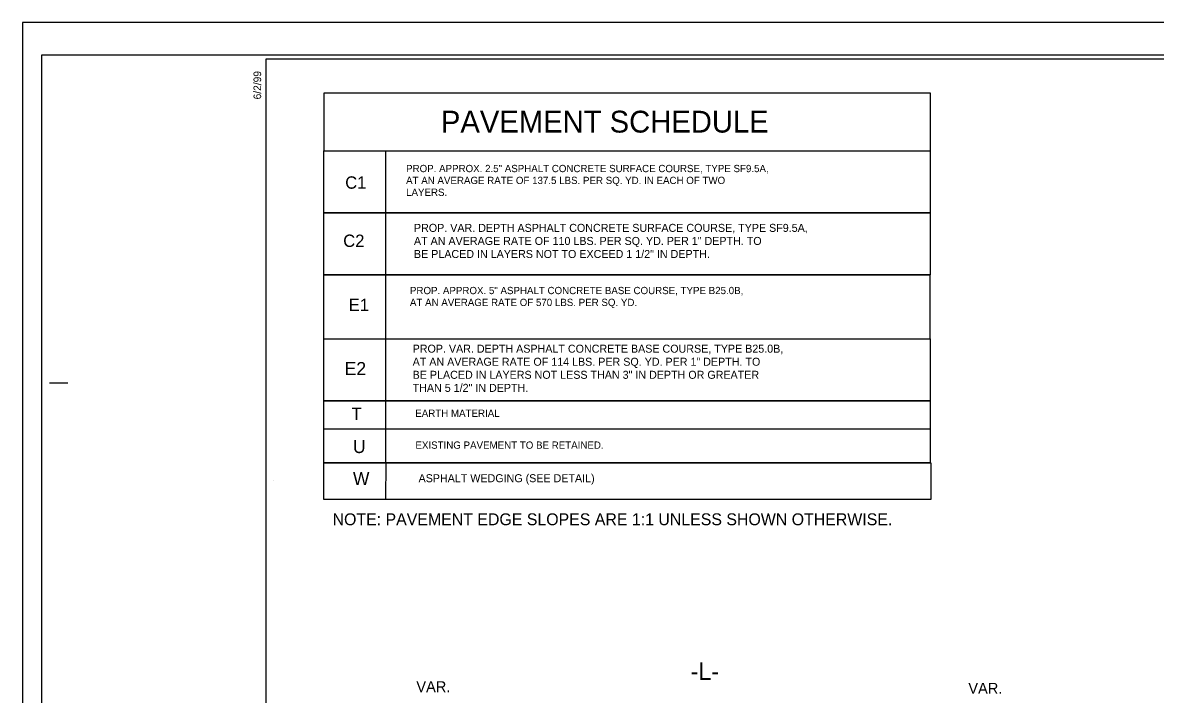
# Model space of a CAD drawing. Extents: x 1818040 to 1825768, y 638918 to 648046.
# Drawn here: x 1820393 to 1821171, y 646022 to 646483 of the extents above; entities that cross this region are included whole.
import ezdxf

# ---------------------------------------------------------------- set-up
doc = ezdxf.new("R2010")
doc.units = 0
for name, color, linetype in [('Prop Pavement Schedule Description CELL', 7, 'Continuous'), ('Sheet Data Field CELL', 7, 'Continuous'), ('Sheet Plot Border Inside CELL', 7, 'Continuous'), ('Sheet Plot Border Outside CELL', 7, 'Continuous'), ('Sheet Typical CELL', 7, 'Continuous')]:
    doc.layers.add(name, color=color, linetype=linetype)

msp = doc.modelspace()

# ---------------------------------------------------------------- linework, layer by layer
at = {"layer": 'Prop Pavement Schedule Description CELL'}
for p, q in [((1820599.79, 646352.71), (1820999.8, 646352.71)), ((1820599.79, 646310.1), (1821016.4, 646310.1)), ((1820599.79, 646266.3), (1820599.79, 646310.1)), ((1820642.4, 646266.3), (1820642.4, 646310.1)), ((1821016.4, 646266.3), (1821016.4, 646310.1)), ((1820599.79, 646204.46), (1821016.4, 646204.46)), ((1820642.4, 646181.09), (1820642.26, 646155.89)), ((1820565.07, 646169.1), (1820565.07, 646169.1))]:
    msp.add_line(p, q, dxfattribs=at)
for points in [[(1820599.79, 646395.32), (1821016.64, 646395.32), (1821016.64, 646435.08), (1820599.79, 646435.08)], [(1820599.79, 646181.09), (1821016.73, 646181.09), (1821016.73, 646155.89), (1820599.79, 646155.89)]]:
    msp.add_lwpolyline(points, close=True, dxfattribs=at)
for points in [[(1820642.4, 646352.71), (1820599.79, 646352.71), (1820599.79, 646395.32), (1821016.39, 646395.32), (1821016.39, 646352.71), (1820642.4, 646352.71), (1820642.4, 646395.32)], [(1820642.4, 646310.1), (1820599.79, 646310.1), (1820599.79, 646352.71), (1821016.39, 646352.71), (1821016.39, 646310.1), (1820642.4, 646310.1), (1820642.4, 646352.71)], [(1820642.4, 646223.69), (1820599.79, 646223.69), (1820599.79, 646266.3), (1821016.4, 646266.3), (1821016.4, 646223.69), (1820642.4, 646223.69), (1820642.4, 646266.3)], [(1820642.4, 646181.09), (1820599.79, 646181.09), (1820599.79, 646223.69), (1821016.4, 646223.69), (1821016.4, 646181.09), (1820642.4, 646181.09), (1820642.4, 646223.69)]]:
    msp.add_lwpolyline(points, dxfattribs=at)
at = {"layer": 'Sheet Plot Border Inside CELL'}
msp.add_lwpolyline([(1822072.43, 646461.05), (1820405.93, 646461.05), (1820405.93, 645405.95), (1822072.43, 645405.95)], close=True, dxfattribs=at)
at = {"layer": 'Sheet Plot Border Outside CELL'}
msp.add_lwpolyline([(1822076.93, 646483.5), (1820392.93, 646483.5), (1820392.93, 645383.5), (1822076.93, 645383.5)], close=True, dxfattribs=at)
at = {"layer": 'Sheet Typical CELL'}
for p, q in [((1822076.93, 646483.5), (1820392.93, 646483.5)), ((1820392.93, 646483.5), (1820392.93, 645383.5)), ((1820411.43, 646236), (1820423.93, 646236))]:
    msp.add_line(p, q, dxfattribs=at)
msp.add_lwpolyline([(1822059.93, 646458.5), (1820559.93, 646458.5), (1820559.93, 645408.5), (1822059.93, 645408.5)], close=True, dxfattribs=at)

# ---------------------------------------------------------------- texts
at = {"layer": 'Prop Pavement Schedule Description CELL'}
for s, height, p in [('PAVEMENT SCHEDULE', 15, (1820680.27, 646407.95)), ('PROP. APPROX. 2.5" ASPHALT CONCRETE SURFACE COURSE, TYPE SF9.5A, ', 5, (1820656.35, 646380.75)), ('C1', 8.506, (1820614.52, 646369.37)), ('AT AN AVERAGE RATE OF 137.5 LBS. PER SQ. YD. IN EACH OF TWO ', 5, (1820656.35, 646372.59)), ('LAYERS.', 5, (1820656.35, 646364.43)), ('PROP. VAR. DEPTH ASPHALT CONCRETE SURFACE COURSE, TYPE SF9.5A,', 5.5, (1820661.74, 646339.71)), ('C2', 8.506, (1820613.16, 646329.34)), ('AT AN AVERAGE RATE OF 110 LBS. PER SQ. YD. PER 1" DEPTH. TO', 5.5, (1820661.74, 646330.73)), ('BE PLACED IN LAYERS NOT TO EXCEED 1 1/2" IN DEPTH.', 5.5, (1820661.74, 646321.76)), ('PROP. APPROX. 5" ASPHALT CONCRETE BASE COURSE, TYPE B25.0B, ', 5, (1820658.99, 646296.91)), ('E1', 8.506, (1820616.97, 646285.32)), ('AT AN AVERAGE RATE OF 570 LBS. PER SQ. YD. ', 5, (1820658.99, 646288.75)), ('PROP. VAR. DEPTH ASPHALT CONCRETE BASE COURSE, TYPE B25.0B,', 5.5, (1820660.84, 646256.68)), ('AT AN AVERAGE RATE OF 114 LBS. PER SQ. YD. PER 1" DEPTH. TO', 5.5, (1820660.84, 646247.71)), ('E2', 8.983, (1820614.17, 646241.28)), ('BE PLACED IN LAYERS NOT LESS THAN 3" IN DEPTH OR GREATER', 5.5, (1820660.84, 646238.74)), ('THAN 5 1/2" IN DEPTH.', 5.5, (1820660.84, 646229.76)), ('T', 8.51, (1820618.82, 646210.35)), ('EARTH MATERIAL ', 5, (1820662.66, 646212.58)), ('U', 8.98, (1820619.85, 646187.7)), ('EXISTING PAVEMENT TO BE RETAINED.', 5, (1820662.77, 646190.66)), ('W', 8.98, (1820619.84, 646165.73)), ('ASPHALT WEDGING (SEE DETAIL)', 5.5, (1820664.9, 646167.67)), ('NOTE: PAVEMENT EDGE SLOPES ARE 1:1 UNLESS SHOWN OTHERWISE.', 8.1625, (1820605.84, 646138.11))]:
    msp.add_text(s, height=height, dxfattribs=at).set_placement(p)
at = {"layer": 'Sheet Data Field CELL'}
for s, height, p in [('-L-', 12, (1820851.78, 646031.78)), ('VAR. ', 7.5, (1820663.38, 646023.38)), ('VAR. ', 7.5, (1821042.58, 646022.28))]:
    msp.add_text(s, height=height, dxfattribs=at).set_placement(p)
at = {"layer": 'Sheet Typical CELL'}
msp.add_text('6/2/99', height=5.25, rotation=90, dxfattribs=at).set_placement((1820556.78, 646430.75))

doc.saveas('drawing.dxf')
